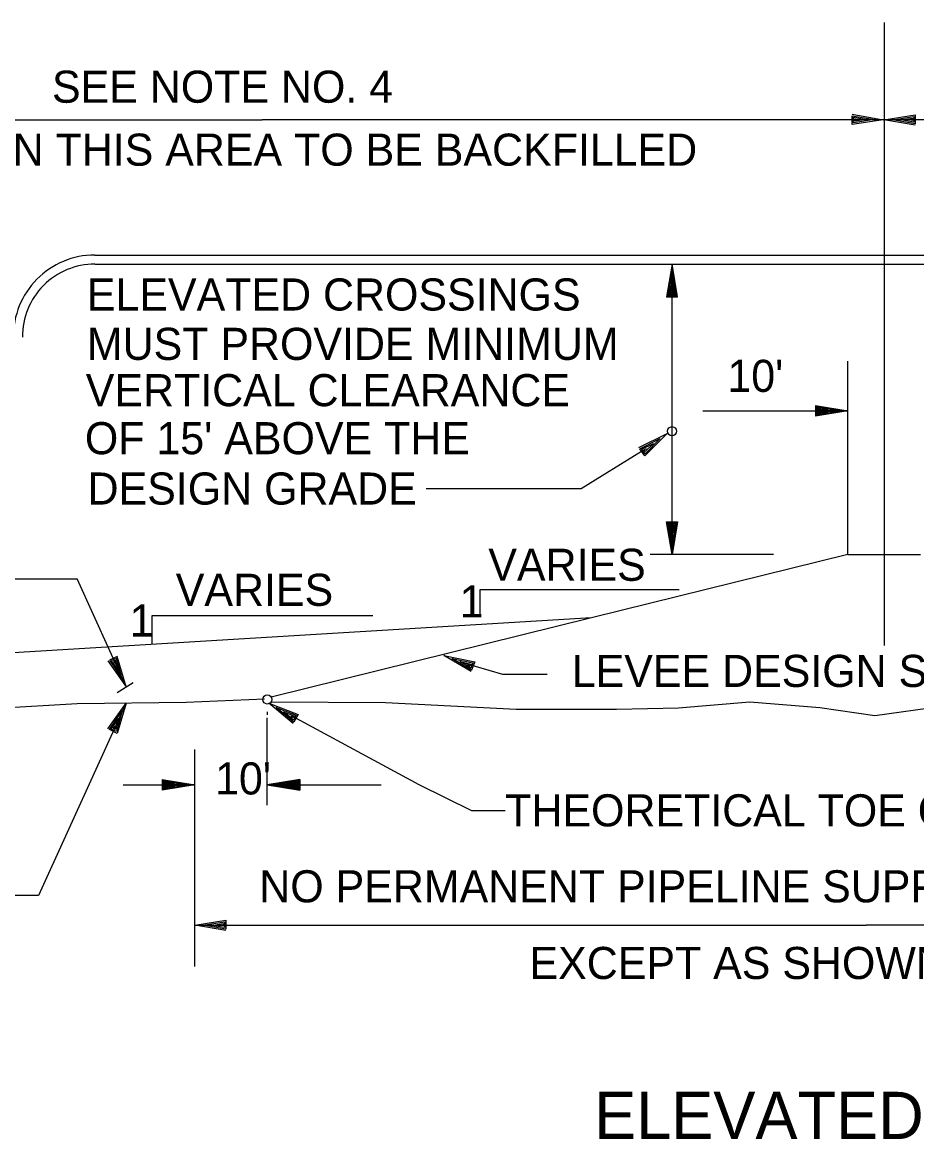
# Model space of a CAD drawing. Extents: x 2127959 to 2137375, y 2146193 to 2153470.
# Drawn here: x 2130277 to 2131195, y 2151641 to 2152787 of the extents above; entities that cross this region are included whole.
import ezdxf

# ---------------------------------------------------------------- set-up
doc = ezdxf.new("R2010")
doc.units = 0
for name, color, linetype in [('Level 1', 7, 'Continuous'), ('Level 3', 7, 'Continuous'), ('Level 5', 7, 'Continuous'), ('Level 50', 7, 'Continuous'), ('Level 63', 7, 'Continuous')]:
    doc.layers.add(name, color=color, linetype=linetype)

msp = doc.modelspace()

# ---------------------------------------------------------------- linework, layer by layer
at = {"layer": 'Level 1'}
for p, q in [((2130850.783, 2152309.06), (2130912.694, 2152347.274)), ((2130691.666, 2152309.06), (2130850.783, 2152309.06)), ((2131124.455, 2152241.498), (2130862.669, 2152176.671)), ((2131124.455, 2152241.498), (2130862.669, 2152176.671)), ((2131124.455, 2152241.498), (2130862.669, 2152176.671)), ((2131124.455, 2152241.498), (2131198.918, 2152241.498)), ((2131124.455, 2152241.498), (2131198.918, 2152241.498)), ((2131124.455, 2152241.498), (2131198.918, 2152241.498)), ((2130080.518, 2152216.542), (2130333.642, 2152216.542)), ((2130383.784, 2152105.581), (2130333.642, 2152216.542)), ((2130861.39, 2152176.343), (2130268.115, 2152140.601)), ((2130861.39, 2152176.343), (2130268.115, 2152140.601)), ((2130861.39, 2152176.343), (2130268.115, 2152140.601)), ((2130862.669, 2152176.671), (2130532.744, 2152094.955)), ((2130770.438, 2152118.199), (2130728.374, 2152130.383)), ((2130374.796, 2152099.757), (2130391.223, 2152109.912)), ((2130815.822, 2152118.199), (2130770.438, 2152118.199)), ((2130294.121, 2151891.491), (2130119.004, 2151891.491))]:
    msp.add_line(p, q, dxfattribs=at)
at = {"layer": 'Level 3'}
for p, q in [((2131161.687, 2152787.409), (2131161.687, 2152147.973)), ((2129884.975, 2152687.419), (2130523.327, 2152687.419)), ((2131161.687, 2152687.419), (2130523.327, 2152687.419)), ((2131161.687, 2152687.675), (2131787.674, 2152687.675)), ((2130351.811, 2152548.663), (2131942.143, 2152548.663)), ((2130351.811, 2152548.663), (2131942.143, 2152548.663)), ((2130351.811, 2152548.663), (2131942.143, 2152548.663)), ((2130352.15, 2152539.354), (2131936.796, 2152539.354)), ((2130352.15, 2152539.354), (2131936.796, 2152539.354)), ((2130352.15, 2152539.354), (2131936.796, 2152539.354)), ((2130943.982, 2152539.354), (2130938.415, 2152505.891)), ((2130943.982, 2152241.498), (2130943.982, 2152539.354)), ((2130943.982, 2152539.354), (2130943.982, 2152505.891)), ((2130949.568, 2152505.891), (2130943.982, 2152539.354)), ((2130948.84, 2152506.456), (2130944.491, 2152532.536)), ((2130944.491, 2152532.536), (2130944.626, 2152507.099)), ((2130939.161, 2152506.354), (2130943.449, 2152532.458)), ((2130939.993, 2152506.991), (2130942.927, 2152526.011)), ((2130942.927, 2152526.011), (2130942.805, 2152507.827)), ((2130943.449, 2152532.458), (2130943.462, 2152507.081)), ((2130948.034, 2152507.203), (2130945.025, 2152526.146)), ((2130945.025, 2152526.146), (2130945.311, 2152507.811)), ((2130940.828, 2152507.737), (2130942.183, 2152517.331)), ((2130942.183, 2152517.331), (2130942.034, 2152508.394)), ((2130947.246, 2152507.798), (2130945.769, 2152517.313)), ((2130945.769, 2152517.313), (2130945.891, 2152508.38)), ((2130938.415, 2152505.891), (2130949.568, 2152505.891)), ((2130943.462, 2152506.443), (2130939.161, 2152506.354)), ((2130943.462, 2152507.081), (2130939.993, 2152506.991)), ((2130942.805, 2152507.827), (2130940.828, 2152507.737)), ((2130944.609, 2152506.397), (2130948.84, 2152506.456)), ((2130944.626, 2152507.099), (2130948.034, 2152507.203)), ((2130945.311, 2152507.811), (2130947.246, 2152507.798)), ((2131124.455, 2152241.498), (2131124.455, 2152439.619)), ((2131124.455, 2152241.498), (2131124.455, 2152439.619)), ((2131124.455, 2152241.498), (2131124.455, 2152439.619)), ((2130975.572, 2152388.834), (2131124.455, 2152388.834)), ((2131090.975, 2152394.404), (2131090.975, 2152383.248)), ((2131090.975, 2152394.404), (2131124.455, 2152388.834)), ((2131124.455, 2152388.834), (2131090.975, 2152388.834)), ((2131124.455, 2152388.834), (2131090.975, 2152383.248)), ((2131091.455, 2152383.934), (2131119.451, 2152388.418)), ((2131091.602, 2152388.284), (2131091.455, 2152383.934)), ((2131091.633, 2152393.423), (2131091.586, 2152389.312)), ((2131091.586, 2152389.312), (2131119.495, 2152389.193)), ((2131092.287, 2152388.284), (2131092.272, 2152384.709)), ((2131092.272, 2152384.709), (2131113.047, 2152387.82)), ((2131119.451, 2152388.418), (2131092.287, 2152388.284)), ((2131092.346, 2152393.481), (2131092.33, 2152389.801)), ((2131092.33, 2152389.801), (2131113.239, 2152389.668)), ((2131119.495, 2152389.193), (2131092.346, 2152393.481)), ((2131113.047, 2152387.82), (2131092.988, 2152387.54)), ((2131092.988, 2152387.54), (2131093.06, 2152385.483)), ((2131093.06, 2152385.483), (2131104.008, 2152386.958)), ((2131113.239, 2152389.668), (2131093.075, 2152392.649)), ((2131093.075, 2152392.649), (2131093.075, 2152390.606)), ((2131093.075, 2152390.606), (2131103.857, 2152390.413)), ((2131104.008, 2152386.958), (2131093.836, 2152387.001)), ((2131093.836, 2152387.001), (2131093.849, 2152386.183)), ((2131093.849, 2152386.183), (2131096.947, 2152386.435)), ((2131103.857, 2152390.413), (2131093.866, 2152392.021)), ((2131093.866, 2152392.021), (2131093.894, 2152391.187)), ((2131093.894, 2152391.187), (2131097.068, 2152391.098)), ((2130938.415, 2152274.979), (2130949.568, 2152274.979)), ((2130943.982, 2152241.498), (2130938.415, 2152274.979)), ((2130943.462, 2152274.429), (2130939.161, 2152274.502)), ((2130939.161, 2152274.502), (2130943.449, 2152248.411)), ((2130943.462, 2152273.789), (2130939.993, 2152273.878)), ((2130939.993, 2152273.878), (2130942.927, 2152254.845)), ((2130942.805, 2152273.043), (2130940.828, 2152273.119)), ((2130940.828, 2152273.119), (2130942.183, 2152263.54)), ((2130942.183, 2152263.54), (2130942.034, 2152272.478)), ((2130942.927, 2152254.845), (2130942.805, 2152273.043)), ((2130943.449, 2152248.411), (2130943.462, 2152273.789)), ((2130943.982, 2152241.498), (2130943.982, 2152274.979)), ((2130949.568, 2152274.979), (2130943.982, 2152241.498)), ((2130948.84, 2152274.412), (2130944.491, 2152248.338)), ((2130944.491, 2152248.338), (2130944.626, 2152273.773)), ((2130944.609, 2152274.473), (2130948.84, 2152274.412)), ((2130944.626, 2152273.773), (2130948.034, 2152273.668)), ((2130948.034, 2152273.668), (2130945.025, 2152254.726)), ((2130945.025, 2152254.726), (2130945.311, 2152273.061)), ((2130945.311, 2152273.061), (2130947.246, 2152273.073)), ((2130947.246, 2152273.073), (2130945.769, 2152263.556)), ((2130945.769, 2152263.556), (2130945.891, 2152272.491)), ((2131047.949, 2152241.498), (2130921.349, 2152241.498)), ((2130746.764, 2152205.186), (2130746.764, 2152177.427)), ((2130951.377, 2152205.186), (2130746.764, 2152205.186)), ((2130410.339, 2152178.566), (2130410.339, 2152149.284)), ((2130636.985, 2152178.566), (2130410.339, 2152178.566)), ((2130528.739, 2152079.869), (2130528.739, 2152078.797)), ((2130528.739, 2152079.869), (2130528.739, 2152078.797)), ((2130528.739, 2152079.869), (2130528.739, 2152078.797)), ((2130528.739, 2152078.797), (2130528.739, 2152076.964)), ((2130528.739, 2152078.797), (2130528.739, 2152076.964)), ((2130528.739, 2152078.797), (2130528.739, 2152076.964)), ((2130528.739, 2151984.244), (2130528.739, 2152073.687)), ((2130528.739, 2151984.244), (2130528.739, 2152073.687)), ((2130528.739, 2151984.244), (2130528.739, 2152073.687)), ((2130454.276, 2151818.472), (2130454.276, 2152041.223)), ((2130454.276, 2151818.472), (2130454.276, 2152041.223)), ((2130454.276, 2151818.472), (2130454.276, 2152041.223)), ((2130420.799, 2152010.635), (2130420.799, 2151999.479)), ((2130420.799, 2152010.635), (2130454.276, 2152005.049)), ((2130421.464, 2152009.65), (2130421.41, 2152005.526)), ((2130421.41, 2152005.526), (2130449.324, 2152005.404)), ((2130422.167, 2152009.712), (2130422.151, 2152006.031)), ((2130422.151, 2152006.031), (2130443.06, 2152005.883)), ((2130449.324, 2152005.404), (2130422.167, 2152009.712)), ((2130443.06, 2152005.883), (2130422.892, 2152008.876)), ((2130422.892, 2152008.876), (2130422.892, 2152006.82)), ((2130422.892, 2152006.82), (2130433.681, 2152006.639)), ((2130433.681, 2152006.639), (2130423.697, 2152008.234)), ((2130423.697, 2152008.234), (2130423.72, 2152007.416)), ((2130423.72, 2152007.416), (2130426.886, 2152007.311)), ((2130562.213, 2152010.635), (2130528.739, 2152005.049)), ((2130561.519, 2152009.946), (2130534.394, 2152005.435)), ((2130534.394, 2152005.435), (2130560.991, 2152005.748)), ((2130560.94, 2152009.249), (2130539.783, 2152005.852)), ((2130539.783, 2152005.852), (2130560.195, 2152006.403)), ((2130560.135, 2152008.428), (2130547.781, 2152006.583)), ((2130547.781, 2152006.583), (2130559.513, 2152006.777)), ((2130559.564, 2152007.789), (2130556.026, 2152007.252)), ((2130559.513, 2152006.777), (2130559.564, 2152007.789)), ((2130560.195, 2152006.403), (2130560.135, 2152008.428)), ((2130560.991, 2152005.748), (2130560.94, 2152009.249)), ((2130561.572, 2152005.837), (2130561.519, 2152009.946)), ((2130562.213, 2152010.635), (2130562.213, 2151999.479)), ((2130380.858, 2152005.049), (2130454.276, 2152005.049)), ((2130454.276, 2152005.049), (2130420.799, 2152005.049)), ((2130454.276, 2152005.049), (2130420.799, 2151999.479)), ((2130421.284, 2152000.165), (2130449.281, 2152004.63)), ((2130421.431, 2152004.497), (2130421.284, 2152000.165)), ((2130422.111, 2152004.511), (2130422.105, 2152000.937)), ((2130422.105, 2152000.937), (2130442.872, 2152004.052)), ((2130449.281, 2152004.63), (2130422.111, 2152004.511)), ((2130442.872, 2152004.052), (2130422.816, 2152003.766)), ((2130422.816, 2152003.766), (2130422.884, 2152001.698)), ((2130422.884, 2152001.698), (2130433.828, 2152003.186)), ((2130433.828, 2152003.186), (2130423.661, 2152003.232)), ((2130423.661, 2152003.232), (2130423.672, 2152002.397)), ((2130423.672, 2152002.397), (2130426.77, 2152002.649)), ((2130528.739, 2152005.049), (2130645.625, 2152005.049)), ((2130528.739, 2152005.049), (2130562.213, 2152005.049)), ((2130528.739, 2152005.049), (2130562.213, 2151999.479)), ((2130561.669, 2152000.224), (2130534.486, 2152004.527)), ((2130534.486, 2152004.527), (2130560.94, 2152004.527)), ((2130561.024, 2152000.908), (2130539.917, 2152004.11)), ((2130539.917, 2152004.11), (2130560.277, 2152003.902)), ((2130560.262, 2152001.698), (2130547.942, 2152003.469)), ((2130547.942, 2152003.469), (2130559.599, 2152003.275)), ((2130559.75, 2152002.293), (2130556.015, 2152002.787)), ((2130559.599, 2152003.275), (2130559.75, 2152002.293)), ((2130560.277, 2152003.902), (2130560.262, 2152001.698)), ((2130560.94, 2152004.527), (2130561.024, 2152000.908)), ((2130561.614, 2152004.511), (2130561.669, 2152000.224)), ((2130454.276, 2151861.007), (2131143.071, 2151861.007)), ((2130454.276, 2151861.007), (2131143.071, 2151861.007)), ((2130454.276, 2151861.007), (2131143.071, 2151861.007)), ((2131831.86, 2151861.007), (2131143.071, 2151861.007)), ((2131831.86, 2151861.007), (2131143.071, 2151861.007)), ((2131831.86, 2151861.007), (2131143.071, 2151861.007))]:
    msp.add_line(p, q, dxfattribs=at)
for points in [[(2130383.891, 2152089.026), (2130294.121, 2151891.491)], [(2130553.757, 2152075.907), (2130684.099, 2152005.217), (2130738.339, 2151978.633), (2130772.654, 2151978.633)]]:
    msp.add_lwpolyline(points, dxfattribs=at)
for centre, radius in [((2130943.984, 2152367.88), 4.662), ((2130528.738, 2152092.572), 4.654), ((2130528.738, 2152092.572), 4.654), ((2130528.738, 2152092.572), 4.654)]:
    msp.add_circle(centre, radius, dxfattribs=at)
for centre, radius, start, end in [((2130351.887, 2152464.891), 83.772, 90.144292, 180.356647), ((2130351.887, 2152464.891), 83.772, 90.144292, 180.356647), ((2130351.887, 2152464.891), 83.772, 90.144292, 180.356647), ((2130351.888, 2152464.889), 74.466, 90.006547, 180.307747), ((2130351.888, 2152464.889), 74.466, 90.006547, 180.307747), ((2130351.888, 2152464.889), 74.466, 90.006547, 180.307747)]:
    msp.add_arc(centre, radius, start, end, dxfattribs=at)
at = {"layer": 'Level 5'}
for p, q in [((2130242.698, 2152083.189), (2130333.717, 2152088.477)), ((2130242.698, 2152083.189), (2130333.717, 2152088.477)), ((2130242.698, 2152083.189), (2130333.717, 2152088.477)), ((2130333.717, 2152088.477), (2130445.464, 2152089.685)), ((2130333.717, 2152088.477), (2130445.464, 2152089.685)), ((2130333.717, 2152088.477), (2130445.464, 2152089.685)), ((2130445.464, 2152089.685), (2130525.97, 2152093.289)), ((2130445.464, 2152089.685), (2130525.97, 2152093.289)), ((2130445.464, 2152089.685), (2130525.97, 2152093.289)), ((2130532.629, 2152090.025), (2130650.035, 2152089.446)), ((2130532.629, 2152090.025), (2130650.035, 2152089.446)), ((2130532.629, 2152090.025), (2130650.035, 2152089.446)), ((2130650.035, 2152089.446), (2130784.007, 2152082.475)), ((2130650.035, 2152089.446), (2130784.007, 2152082.475)), ((2130650.035, 2152089.446), (2130784.007, 2152082.475)), ((2130950.433, 2152083.921), (2131023.718, 2152090.161)), ((2130950.433, 2152083.921), (2131023.718, 2152090.161)), ((2130950.433, 2152083.921), (2131023.718, 2152090.161)), ((2131023.718, 2152090.161), (2131095.517, 2152084.398)), ((2131023.718, 2152090.161), (2131095.517, 2152084.398)), ((2131023.718, 2152090.161), (2131095.517, 2152084.398)), ((2131151.991, 2152075.983), (2131230.701, 2152087.046)), ((2131151.991, 2152075.983), (2131230.701, 2152087.046)), ((2131151.991, 2152075.983), (2131230.701, 2152087.046)), ((2130784.007, 2152082.475), (2130887.05, 2152082.716)), ((2130784.007, 2152082.475), (2130887.05, 2152082.716)), ((2130784.007, 2152082.475), (2130887.05, 2152082.716)), ((2130887.05, 2152082.716), (2130950.433, 2152083.921)), ((2130887.05, 2152082.716), (2130950.433, 2152083.921)), ((2130887.05, 2152082.716), (2130950.433, 2152083.921)), ((2131095.517, 2152084.398), (2131151.991, 2152075.983)), ((2131095.517, 2152084.398), (2131151.991, 2152075.983)), ((2131095.517, 2152084.398), (2131151.991, 2152075.983))]:
    msp.add_line(p, q, dxfattribs=at)
at = {"layer": 'Level 50'}
for p, q in [((2131151.707, 2152687.592), (2131151.707, 2152687.592)), ((2131160.592, 2152687.525), (2131160.592, 2152687.525)), ((2131161.351, 2152687.415), (2131161.351, 2152687.415)), ((2131170.235, 2152687.347), (2131170.235, 2152687.347)), ((2130938.995, 2152365.489), (2130938.995, 2152365.489)), ((2130931.767, 2152360.317), (2130931.767, 2152360.317)), ((2130709.897, 2152137.854), (2130709.897, 2152137.854)), ((2130718.174, 2152134.614), (2130718.174, 2152134.614)), ((2130379.957, 2152113.596), (2130379.957, 2152113.596)), ((2130383.784, 2152105.581), (2130383.784, 2152105.581)), ((2130383.784, 2152088.913), (2130383.784, 2152088.913)), ((2130530.282, 2152088.833), (2130530.282, 2152088.833)), ((2130379.957, 2152080.898), (2130379.957, 2152080.898)), ((2130537.953, 2152084.333), (2130537.953, 2152084.333)), ((2130454.208, 2151860.938), (2130454.208, 2151860.938)), ((2130463.093, 2151860.872), (2130463.093, 2151860.872))]:
    msp.add_line(p, q, dxfattribs=at)
for points in [[(2131128.685, 2152693.049), (2131160.592, 2152687.525), (2131128.619, 2152682.454), (2131128.684, 2152691.504), (2131151.707, 2152687.592), (2131130.006, 2152684.156), (2131130.035, 2152689.968), (2131143.174, 2152687.656), (2131131.38, 2152685.853), (2131131.394, 2152688.241), (2131134.289, 2152687.712)], [(2131193.259, 2152681.89), (2131161.351, 2152687.415), (2131193.324, 2152692.487), (2131193.262, 2152683.434), (2131170.235, 2152687.347), (2131191.939, 2152690.786), (2131191.908, 2152684.973), (2131178.769, 2152687.285), (2131190.565, 2152689.086), (2131190.55, 2152686.698), (2131187.657, 2152687.225)], [(2130909.931, 2152351.198), (2130938.995, 2152365.489), (2130916.103, 2152342.585), (2130910.838, 2152349.942), (2130931.767, 2152360.317), (2130916.23, 2152344.775), (2130912.837, 2152349.497), (2130924.827, 2152355.357), (2130916.344, 2152346.955), (2130914.946, 2152348.9), (2130917.599, 2152350.172)], [(2130365.28, 2152132.164), (2130383.784, 2152105.581), (2130374.859, 2152136.687), (2130366.688, 2152132.81), (2130379.957, 2152113.596), (2130373.906, 2152134.71), (2130368.652, 2152132.228), (2130376.297, 2152121.297), (2130372.947, 2152132.748), (2130370.783, 2152131.729), (2130372.48, 2152129.332)], [(2130737.71, 2152121.27), (2130709.897, 2152137.854), (2130741.576, 2152131.14), (2130738.266, 2152122.71), (2130718.174, 2152134.614), (2130739.667, 2152130.048), (2130737.551, 2152124.631), (2130726.108, 2152131.497), (2130737.781, 2152128.956), (2130736.906, 2152126.727), (2130734.389, 2152128.254)], [(2130365.28, 2152062.33), (2130383.784, 2152088.913), (2130374.859, 2152057.807), (2130366.688, 2152061.684), (2130379.957, 2152080.898), (2130373.906, 2152059.784), (2130368.652, 2152062.266), (2130376.297, 2152073.197), (2130372.947, 2152061.746), (2130370.783, 2152062.765), (2130372.48, 2152065.162)], [(2130555.16, 2152068.095), (2130530.282, 2152088.833), (2130560.521, 2152077.234), (2130555.934, 2152069.428), (2130537.953, 2152084.333), (2130558.464, 2152076.46), (2130555.531, 2152071.445), (2130545.303, 2152080.008), (2130556.426, 2152075.672), (2130555.217, 2152073.606), (2130552.976, 2152075.517)], [(2130486.116, 2151855.416), (2130454.208, 2151860.938), (2130486.179, 2151866.01), (2130486.117, 2151856.958), (2130463.093, 2151860.872), (2130484.795, 2151864.309), (2130484.763, 2151858.497), (2130471.625, 2151860.809), (2130483.419, 2151862.611), (2130483.408, 2151860.221), (2130480.511, 2151860.75)]]:
    msp.add_lwpolyline(points, dxfattribs=at)

# ---------------------------------------------------------------- texts
at = {"layer": 'Level 1'}
for s, p in [('SEE NOTE NO. 4', (2130307.828, 2152704.917)), ('EXCAVATION IN THIS AREA TO BE BACKFILLED', (2129959.133, 2152640.298)), ('ELEVATED CROSSINGS ', (2130343.595, 2152491.7)), ('MUST PROVIDE MINIMUM', (2130343.596, 2152441.023)), ("10'", (2131000.724, 2152408.196)), ('VERTICAL CLEARANCE ', (2130342.461, 2152393.523)), ("OF 15' ABOVE THE", (2130341.56, 2152344.24)), ('DESIGN GRADE', (2130344.351, 2152292.575)), ('VARIES', (2130755.457, 2152214.349)), ('VARIES', (2130434.808, 2152188.661)), ('1', (2130726.054, 2152176.748)), ('1', (2130387.496, 2152157.119)), ('LEVEE DESIGN SECTION', (2130841.041, 2152105.442)), ("10'", (2130475.162, 2151995.1)), ('THEORETICAL TOE OF LEVEE', (2130772.775, 2151962.355)), ('NO PERMANENT PIPELINE SUPPORTS IN THIS AREA', (2130520.502, 2151884.394)), ('EXCEPT AS SHOWN ON DWG. 4', (2130797.683, 2151805.737))]:
    msp.add_text(s, height=32.931, dxfattribs=at).set_placement(p)
at = {"layer": 'Level 63'}
msp.add_text('ELEVATED  CROSSING', height=48.4, dxfattribs=at).set_placement((2130864.001, 2151641.589))

doc.saveas('drawing.dxf')
